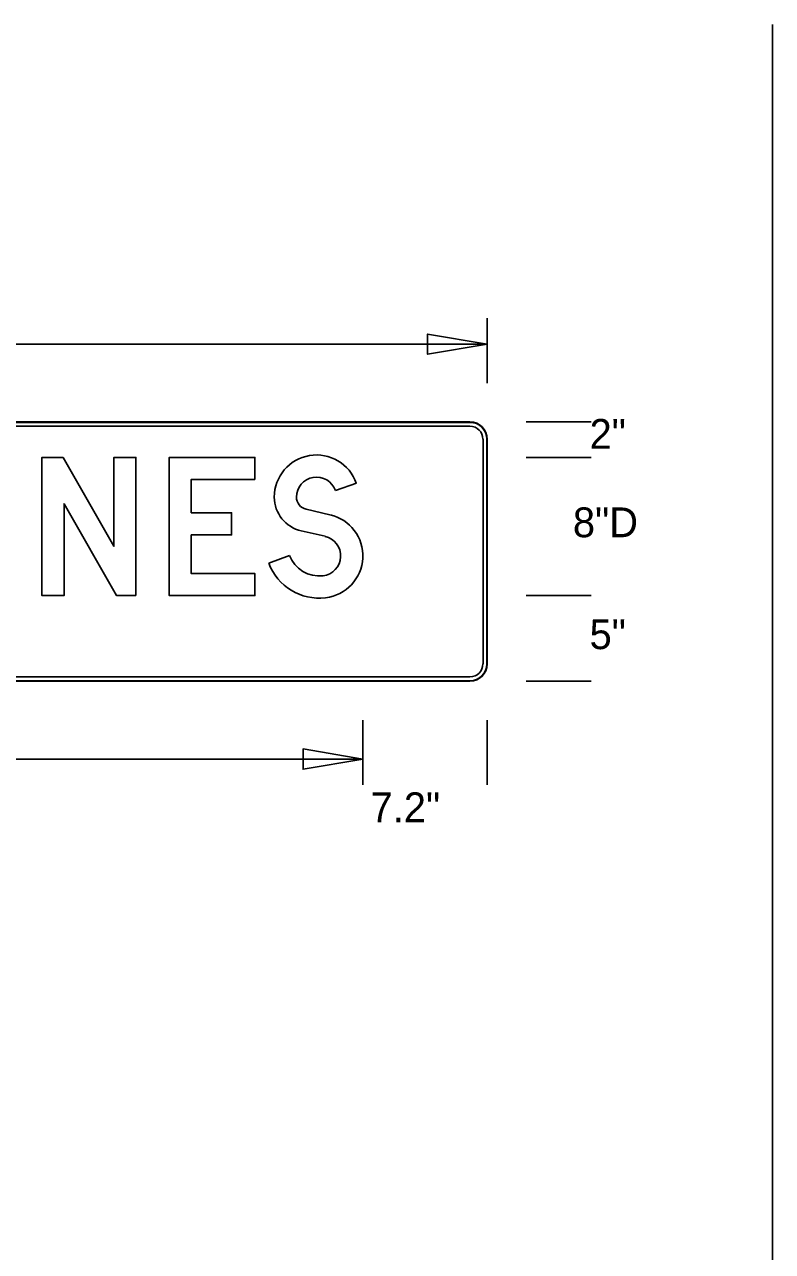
# Model space of a CAD drawing. Extents: x 0 to 770, y 0 to 495.
# Drawn here: x 489.7 to 577.5, y 350.9 to 495 of the extents above; entities that cross this region are included whole.
import ezdxf

# ---------------------------------------------------------------- set-up
doc = ezdxf.new("R2010")
doc.units = 0
for name, color, linetype in [('Dimension', 7, 'Continuous'), ('GSBWFill', 7, 'Continuous'), ('GSColorFill', 7, 'Continuous'), ('GSDims', 7, 'Continuous'), ('GSOutline', 7, 'Continuous'), ('SheetLines_dp', 7, 'Continuous'), ('TextStructures', 7, 'Continuous')]:
    doc.layers.add(name, color=color, linetype=linetype)

msp = doc.modelspace()

# ---------------------------------------------------------------- linework, layer by layer
at = {"layer": 'Dimension'}
for points in [[(544.02, 457.47), (537.01, 458.66), (537.01, 456.28)], [(529.41, 408.75), (522.39, 409.94), (522.39, 407.56)]]:
    msp.add_lwpolyline(points, close=True, dxfattribs=at)
at = {"layer": 'GSBWFill'}
for p, q in [((541.99, 448.34), (412.08, 448.34)), ((541.99, 448.34), (412.08, 448.34)), ((412.08, 447.83), (541.99, 447.83)), ((543.52, 446.31), (543.52, 419.92)), ((544.02, 419.92), (544.02, 446.31)), ((544.02, 419.92), (544.02, 446.31)), ((526.19, 440.28), (528.65, 441.13)), ((525.55, 437.44), (522.75, 438.08)), ((522.18, 435.55), (524.98, 434.91)), ((520.8, 432.67), (518.37, 431.75)), ((412.08, 417.89), (541.99, 417.89)), ((541.99, 418.4), (412.09, 418.4)), ((412.09, 417.89), (541.99, 417.89))]:
    msp.add_line(p, q, dxfattribs=at)
for points in [[(502.78, 427.94), (502.78, 444.17), (500.18, 444.17), (500.18, 433.74), (494.22, 444.17), (491.74, 444.17), (491.74, 427.94), (494.33, 427.94), (494.33, 438.73), (500.5, 427.94)], [(516.74, 441.58), (509.27, 441.58), (509.27, 437.68), (514, 437.68), (514, 435.08), (509.27, 435.08), (509.27, 430.53), (516.74, 430.53), (516.74, 427.94), (506.68, 427.94), (506.68, 444.17), (516.74, 444.17)]]:
    msp.add_lwpolyline(points, close=True, dxfattribs=at)
for centre, radius, start, end in [((541.99, 446.31), 2.03, 0, 90), ((541.99, 446.31), 2.03, 0, 90), ((541.99, 446.31), 1.52, 0, 90), ((523.97, 439.51), 4.95, 19.1395, 180), ((523.97, 439.51), 2.35, 19.1395, 180), ((523.08, 439.51), 4.06, 180, 257.1915), ((523.08, 439.51), 1.46, 180, 257.1915), ((524.46, 432.61), 4.95, 276.7854, 77.1915), ((524.46, 432.61), 2.35, 276.7854, 77.1915), ((524.29, 433.98), 3.73, 200.6442, 276.7854), ((524.29, 433.98), 6.33, 200.6442, 276.7854), ((541.99, 419.92), 2.03, 270, 0), ((541.99, 419.92), 1.52, 270, 0), ((541.99, 419.92), 2.03, 270, 0)]:
    msp.add_arc(centre, radius, start, end, dxfattribs=at)
at = {"layer": 'GSColorFill'}
for p, q in [((541.99, 448.34), (412.08, 448.34)), ((541.99, 448.34), (412.08, 448.34)), ((541.99, 448.34), (412.08, 448.34)), ((412.08, 448.28), (541.99, 448.28)), ((412.08, 447.83), (541.99, 447.83)), ((543.52, 446.31), (543.52, 419.92)), ((543.97, 446.31), (543.97, 419.92)), ((544.02, 419.92), (544.02, 446.31)), ((544.02, 419.92), (544.02, 446.31)), ((544.02, 419.92), (544.02, 446.31)), ((526.19, 440.28), (528.65, 441.13)), ((525.55, 437.44), (522.75, 438.08)), ((522.18, 435.55), (524.98, 434.91)), ((520.8, 432.67), (518.37, 431.75)), ((541.99, 417.94), (412.08, 417.94)), ((412.08, 417.89), (541.99, 417.89)), ((412.08, 417.89), (541.99, 417.89)), ((541.99, 418.4), (412.09, 418.4)), ((412.09, 417.89), (541.99, 417.89))]:
    msp.add_line(p, q, dxfattribs=at)
for points in [[(502.78, 427.94), (502.78, 444.17), (500.18, 444.17), (500.18, 433.74), (494.22, 444.17), (491.74, 444.17), (491.74, 427.94), (494.33, 427.94), (494.33, 438.73), (500.5, 427.94)], [(516.74, 441.58), (509.27, 441.58), (509.27, 437.68), (514, 437.68), (514, 435.08), (509.27, 435.08), (509.27, 430.53), (516.74, 430.53), (516.74, 427.94), (506.68, 427.94), (506.68, 444.17), (516.74, 444.17)]]:
    msp.add_lwpolyline(points, close=True, dxfattribs=at)
for centre, radius, start, end in [((541.99, 446.31), 2.03, 0, 90), ((541.99, 446.31), 2.03, 0, 90), ((541.99, 446.31), 2.03, 0, 90), ((541.99, 446.31), 1.98, 0, 90), ((541.99, 446.31), 1.52, 0, 90), ((523.97, 439.51), 4.95, 19.1395, 180), ((523.97, 439.51), 2.35, 19.1395, 180), ((523.08, 439.51), 4.06, 180, 257.1915), ((523.08, 439.51), 1.46, 180, 257.1915), ((524.46, 432.61), 4.95, 276.7854, 77.1915), ((524.46, 432.61), 2.35, 276.7854, 77.1915), ((524.29, 433.98), 3.73, 200.6442, 276.7854), ((524.29, 433.98), 6.33, 200.6442, 276.7854), ((541.99, 419.92), 2.03, 270, 0), ((541.99, 419.92), 2.03, 270, 0), ((541.99, 419.92), 1.52, 270, 0), ((541.99, 419.92), 2.03, 270, 0), ((541.99, 419.92), 1.98, 270, 0)]:
    msp.add_arc(centre, radius, start, end, dxfattribs=at)
at = {"layer": 'GSDims'}
for p, q in [((544.02, 452.9), (544.02, 460.51)), ((410.05, 457.47), (544.02, 457.47)), ((548.59, 448.34), (556.2, 448.34)), ((548.59, 444.17), (556.2, 444.17)), ((548.59, 444.17), (556.2, 444.17)), ((548.59, 427.94), (556.2, 427.94)), ((548.59, 427.94), (556.2, 427.94)), ((548.59, 417.89), (556.2, 417.89)), ((529.41, 413.32), (529.41, 405.71)), ((529.41, 413.32), (529.41, 405.71)), ((544.02, 413.32), (544.02, 405.71)), ((424.67, 408.75), (529.41, 408.75))]:
    msp.add_line(p, q, dxfattribs=at)
at = {"layer": 'GSOutline'}
for p, q in [((541.99, 448.34), (412.08, 448.34)), ((541.99, 448.34), (412.08, 448.34)), ((541.99, 447.83), (412.08, 447.83)), ((543.52, 419.92), (543.52, 446.31)), ((544.02, 419.92), (544.02, 446.31)), ((544.02, 419.92), (544.02, 446.31)), ((526.19, 440.28), (528.65, 441.13)), ((525.55, 437.44), (522.75, 438.08)), ((522.18, 435.55), (524.98, 434.91)), ((520.8, 432.67), (518.37, 431.75)), ((412.08, 418.4), (541.99, 418.4)), ((412.08, 417.89), (541.99, 417.89)), ((412.08, 417.89), (541.99, 417.89))]:
    msp.add_line(p, q, dxfattribs=at)
for points in [[(502.78, 427.94), (502.78, 444.17), (500.18, 444.17), (500.18, 433.74), (494.22, 444.17), (491.74, 444.17), (491.74, 427.94), (494.33, 427.94), (494.33, 438.73), (500.5, 427.94)], [(516.74, 441.58), (509.27, 441.58), (509.27, 437.68), (514, 437.68), (514, 435.08), (509.27, 435.08), (509.27, 430.53), (516.74, 430.53), (516.74, 427.94), (506.68, 427.94), (506.68, 444.17), (516.74, 444.17)]]:
    msp.add_lwpolyline(points, close=True, dxfattribs=at)
for centre, radius, start, end in [((541.99, 446.31), 2.03, 0, 90), ((541.99, 446.31), 2.03, 0, 90), ((541.99, 446.31), 1.52, 0, 90), ((523.97, 439.51), 4.95, 19.1395, 180), ((523.97, 439.51), 2.35, 19.1395, 180), ((523.08, 439.51), 4.06, 180, 257.1915), ((523.08, 439.51), 1.46, 180, 257.1915), ((524.46, 432.61), 4.95, 276.7854, 77.1915), ((524.46, 432.61), 2.35, 276.7854, 77.1915), ((524.29, 433.98), 3.73, 200.6442, 276.7854), ((524.29, 433.98), 6.33, 200.6442, 276.7854), ((541.99, 419.92), 2.03, 270, 0), ((541.99, 419.92), 1.52, 270, 0), ((541.99, 419.92), 2.03, 270, 0)]:
    msp.add_arc(centre, radius, start, end, dxfattribs=at)
at = {"layer": 'SheetLines_dp'}
msp.add_line((577.5, 0), (577.5, 495), dxfattribs=at)

# ---------------------------------------------------------------- texts
at = {"layer": 'TextStructures'}
for s, p in [('2"', (556.03, 445.18)), ('8"D', (554.07, 434.8)), ('5"', (556.03, 421.66)), ('7.2"', (530.32, 401.34))]:
    msp.add_text(s, height=3.5, dxfattribs=at).set_placement(p)

doc.saveas('drawing.dxf')
